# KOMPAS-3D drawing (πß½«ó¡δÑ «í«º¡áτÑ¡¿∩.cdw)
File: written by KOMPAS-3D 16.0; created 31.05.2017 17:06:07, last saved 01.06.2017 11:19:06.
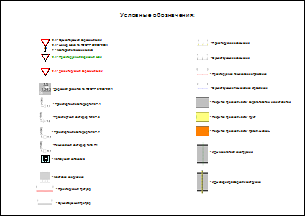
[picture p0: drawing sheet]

Sheet 1: A3, landscape

Title block, sheet 1: scale: 1:1; sheets: 1; sheet format: A3

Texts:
  doruser
  Условные обозначения:
  2.4 - Номер знака по ГОСТ Р 52290-2004
  7 - Месторасположение знака
  2.4 - Существующий дорожный знак
  2.4 - Проектируемый дорожный знак
  2.4 - Демонтируемый дорожный знак
  - Транспортный светофор типа Т.1
  - Транспортный светофор типа Т.5
  - Транспортный светофор типа Т.7
  - Пешеходный светофор типа П.1
  - Автобусная остановка
  - Мостовое сооружение
  - Дорожная разметка по ГОСТ Р 51256-2011
  - Проектируемый тротуар
  - Существующий тротуар
  - Проектируемое освещение
  - Существующее освещение
  - Проектируемое пешеходное ограждение
  - Существующее пешеходное ограждение
  - Покрытие проезжей части: асфальтобетон, цементобетон
  - Покрытие проезжей части: грунт
  - Покрытие проезжей части: гравий, щебень
  - ИДН монолитной конструкции
  - ИДН сборно-разборной конструкции
  POLYLINE_STYLE_0.18_RGB_40_0_0
  POLYLINE_STYLE_0.18_RGB_0_0_0
  Без внутренней рамки.
Dimensions and other numbers on the sheet: 2; 4; 6; 8; 1:1; 1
